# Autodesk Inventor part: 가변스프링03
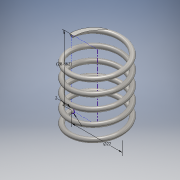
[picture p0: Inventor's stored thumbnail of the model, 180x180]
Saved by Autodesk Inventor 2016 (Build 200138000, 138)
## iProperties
Created: 2015-11
Part Number: 가변스프링03
Material: 스테인레스 스틸
Document SubType Name: Modeling
Designer: eco
Density: 8 g/cm^3
Appearance: 반연마
Mass: 8.55949 g
Surface Area: 21.6802 cm^2
Volume: 1.06994 cm^3
Author: eco
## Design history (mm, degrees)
sketch "스케치1"
  geometry: L1 (0, 0)-(11, 0); L2 (11, 0)-(11, 29.223); L3 (11, 29.223)-(0, 29.223); L4 (0, 29.223)-(0, 0); C1 r 1 at (11, 0)
  constraints: 8 end point, 2 parallel, 1 centre point, 1 coincident, 1 horizontal, 1 perpendicular
  dimensions: "d0" = 2 diameter of C1; "d1" = 22 diameter of L2 L4; "d2" = 29.22346 distance of L1.end L2.end (derived)
feature "코일1" pitch "d3" = 10; turns "d5" = 5; dims "d4" = 29.22346 (= d2), "d6" = 0, angle "d7" = 90 deg, angle "d8" = 90 deg, "d9" = 0, "d10" = 0
sketch "스케치2"
  geometry: L1 (-12, 0)-(-10, 0) reference; 1 further point
  constraints: 1 horizontal alignment
extrude "돌출1" cut sketch "스케치2" stored distance "d11" = 10; taper "d12" = 0 deg
node "작업 평면1"
sketch "스케치3"
  geometry: L1 (1, 0)-(-1, 0) reference; 1 further point
  constraints: 1 horizontal alignment
extrude "돌출2" cut sketch "스케치3" stored distance "d14" = 10; taper "d15" = 0 deg
node "솔리드1"
node "절단 모서리 투영1"
node "절단 모서리 투영2"
other parameters: "d13" = 0
